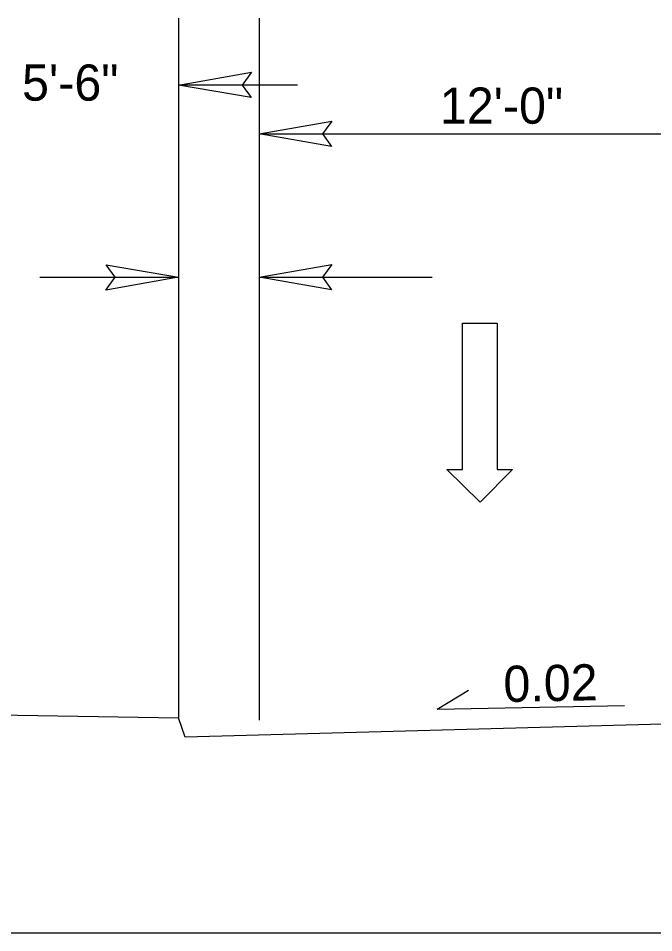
# Model space of a CAD drawing. Extents: x 1904401 to 1905163, y 193929 to 194736.
# Drawn here: x 1904553.44 to 1904569.23, y 194429.04 to 194451.77 of the extents above; entities that cross this region are included whole.
import ezdxf

# ---------------------------------------------------------------- set-up
doc = ezdxf.new("R2010")
doc.units = 0
for name, color, linetype in [('Prop Dimension', 7, 'Continuous'), ('Prop Dimension Text', 7, 'Continuous'), ('Prop Lane Arrow CELL', 7, 'Continuous'), ('Prop Terminator CELL', 7, 'Continuous'), ('Typical Pavement Slope CELL', 7, 'Continuous'), ('Typical Pavement Slope Information CELL', 7, 'Continuous'), ('Typical Sidewalk and Rail CELL', 7, 'Continuous')]:
    doc.layers.add(name, color=color, linetype=linetype)

msp = doc.modelspace()

# ---------------------------------------------------------------- linework, layer by layer
at = {"layer": 'Prop Dimension'}
for p, q in [((1904557.422, 194451.774), (1904557.422, 194434.345)), ((1904559.422, 194451.774), (1904559.422, 194434.319)), ((1904560.378, 194450.111), (1904557.422, 194450.111)), ((1904559.422, 194449.399), (1904559.422, 194434.943)), ((1904559.422, 194449.399), (1904559.422, 194434.943)), ((1904559.422, 194448.899), (1904571.422, 194448.899)), ((1904559.422, 194448.899), (1904559.422, 194434.448)), ((1904553.968, 194445.335), (1904557.422, 194445.335)), ((1904559.422, 194445.335), (1904563.723, 194445.335)), ((1904557.422, 194441.29), (1904557.422, 194434.345))]:
    msp.add_line(p, q, dxfattribs=at)
at = {"layer": 'Prop Lane Arrow CELL'}
for p, q in [((1904564.481, 194444.19), (1904565.337, 194444.19)), ((1904564.481, 194440.559), (1904564.481, 194444.19)), ((1904565.337, 194444.19), (1904565.337, 194440.559)), ((1904564.922, 194439.742), (1904564.092, 194440.559)), ((1904564.092, 194440.559), (1904564.481, 194440.559)), ((1904565.726, 194440.559), (1904564.922, 194439.742)), ((1904565.337, 194440.559), (1904565.726, 194440.559))]:
    msp.add_line(p, q, dxfattribs=at)
at = {"layer": 'Prop Terminator CELL'}
for points in [[(1904559.222, 194449.801), (1904557.422, 194450.111), (1904559.232, 194450.431), (1904559.002, 194450.111)], [(1904561.222, 194448.589), (1904559.422, 194448.899), (1904561.232, 194449.219), (1904561.002, 194448.899)], [(1904555.622, 194445.645), (1904557.422, 194445.335), (1904555.612, 194445.015), (1904555.842, 194445.335)], [(1904561.222, 194445.025), (1904559.422, 194445.335), (1904561.232, 194445.655), (1904561.002, 194445.335)]]:
    msp.add_lwpolyline(points, close=True, dxfattribs=at)
at = {"layer": 'Typical Pavement Slope CELL'}
msp.add_line((1904579.661, 194434.504), (1904557.583, 194433.898), dxfattribs=at)
at = {"layer": 'Typical Pavement Slope Information CELL'}
for q in [(1904564.63, 194435.066), (1904568.508, 194434.686)]:
    msp.add_line((1904563.847, 194434.593), q, dxfattribs=at)
at = {"layer": 'Typical Sidewalk and Rail CELL'}
for p, q in [((1904552.084, 194434.468), (1904557.422, 194434.379)), ((1904557.583, 194433.898), (1904557.422, 194434.379)), ((1904550.75, 194429.038), (1904609.594, 194429.038))]:
    msp.add_line(p, q, dxfattribs=at)

# ---------------------------------------------------------------- texts
at = {"layer": 'Prop Dimension Text'}
msp.add_text('5\'-6"', height=0.9, rotation=360, dxfattribs=at).set_placement((1904553.529, 194449.726))
msp.add_text('12\'-0"', height=0.9, dxfattribs=at).set_placement((1904563.915, 194449.153))
at = {"layer": 'Typical Pavement Slope Information CELL'}
msp.add_text('0.02', height=0.9, rotation=1.1457, dxfattribs=at).set_placement((1904565.505, 194434.772))

doc.saveas('drawing.dxf')
